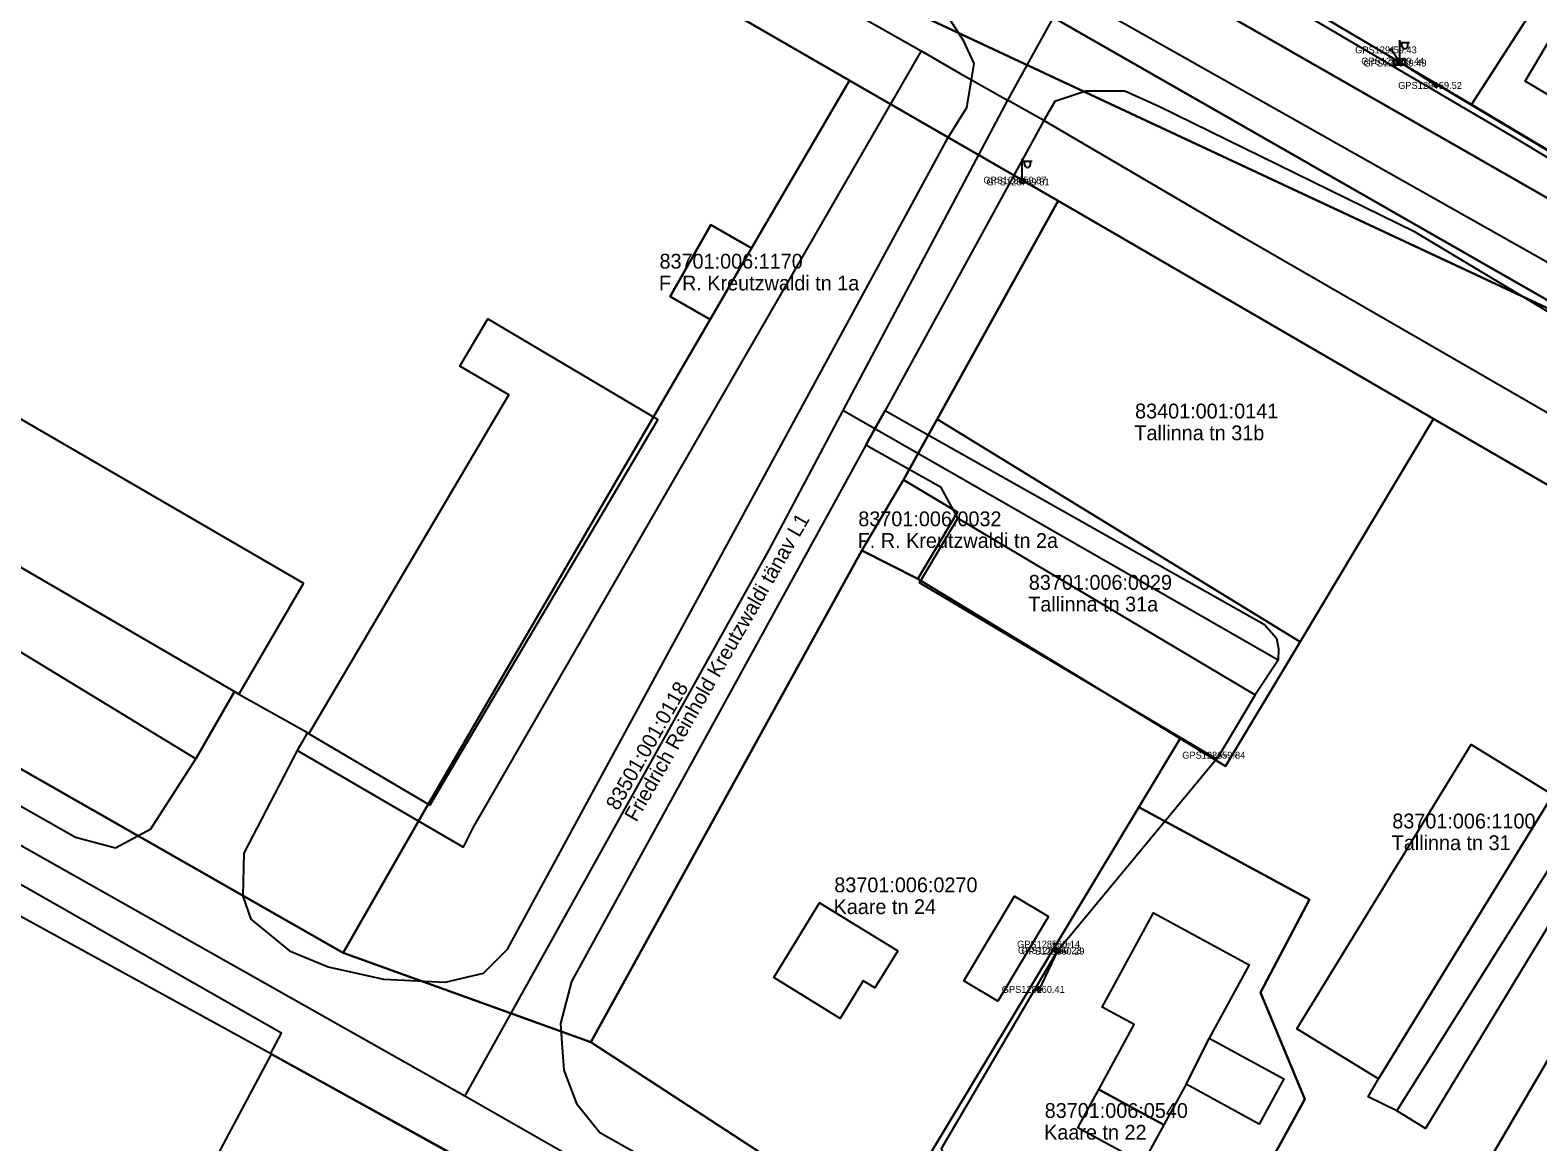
# Model space of a CAD drawing. Extents: x 580119 to 583377, y 6518915 to 6520820.
# Drawn here: x 581401 to 581553.7, y 6519827.6 to 6519940.2 of the extents above; entities that cross this region are included whole.
import ezdxf

# ---------------------------------------------------------------- set-up
doc = ezdxf.new("R2010")
doc.units = 0
for name, color, linetype in [('ELRAJATISMP', 7, 'Continuous'), ('Hoone Elu- või ühiskondlik hoone', 7, 'Continuous'), ('Hoone Kõrval- või tootmishoone', 7, 'Continuous'), ('Hoone Vare', 7, 'Continuous'), ('L_AADRESS', 7, 'Continuous'), ('MAAMUDEL', 7, 'Continuous'), ('MOOTKORG-EH2000', 7, 'Continuous'), ('MOOTMPUNKT', 7, 'Continuous'), ('MOOTNR', 7, 'Continuous'), ('MPOHULIIN', 7, 'Continuous'), ('PIIR', 7, 'Continuous'), ('POST', 7, 'Continuous'), ('SIOHULIIN', 7, 'Continuous'), ('Tee Kergliiklustee Püsikate', 7, 'Continuous'), ('Tee Liiklusala', 7, 'Continuous'), ('Tee Muu', 7, 'Continuous'), ('Tee Rada Püsikate', 7, 'Continuous'), ('Tee Tugimaantee Püsikate', 7, 'Continuous'), ('Tee Tänav Püsikate', 7, 'Continuous'), ('TUNNUS', 7, 'Continuous')]:
    doc.layers.add(name, color=color, linetype=linetype)

msp = doc.modelspace()

# ---------------------------------------------------------------- linework, layer by layer
at = {"layer": 'ELRAJATISMP'}
for p, q in [((581539.58, 6519937.29), (581539.58, 6519936.69)), ((581539.85, 6519937.29), (581539.85, 6519936.69))]:
    msp.add_line(p, q, dxfattribs=at)
msp.add_lwpolyline([(581539.12, 6519937.29), (581540.31, 6519937.29), (581540.31, 6519936.69), (581539.12, 6519936.69)], close=True, dxfattribs=at)
at = {"layer": 'Hoone Elu- või ühiskondlik hoone'}
for points in [[(581570.8, 6519937.3), (581565.05, 6519927.58), (581552.43, 6519935.06), (581558.18, 6519944.76)], [(581428.69, 6519884.2), (581422.17, 6519872.97), (581382.36, 6519896.1), (581389.59, 6519908.57), (581397.85, 6519903.79), (581397.12, 6519902.55)], [(581555.24, 6519862.76), (581537.58, 6519833.98), (581529.3, 6519839.06), (581546.95, 6519867.85)], [(581488.88, 6519846.95), (581486.57, 6519843.2), (581485.39, 6519843.92), (581483.04, 6519840.1), (581476.32, 6519844.25), (581480.97, 6519851.81)], [(581515.84, 6519829.32), (581509.24, 6519832.92), (581512.82, 6519839.5), (581509.6, 6519841.25), (581514.8, 6519850.82), (581524.48, 6519845.55), (581520.42, 6519838.11), (581518.08, 6519833.44)]]:
    msp.add_lwpolyline(points, close=True, dxfattribs=at)
at = {"layer": 'Hoone Kõrval- või tootmishoone'}
for points in [[(581464.6, 6519900.79), (581441.5, 6519861.7), (581429.23, 6519868.95), (581449.51, 6519903.28), (581444.55, 6519906.21), (581447.36, 6519910.98)], [(581525.08, 6519872.9), (581521.2, 6519866.37), (581517.32, 6519868.67), (581491.08, 6519884.26), (581494.96, 6519890.8)], [(581504.14, 6519850.43), (581499.02, 6519841.86), (581495.58, 6519843.91), (581500.7, 6519852.48)]]:
    msp.add_lwpolyline(points, close=True, dxfattribs=at)
at = {"layer": 'Hoone Vare'}
for points in [[(581518.08, 6519833.44), (581520.42, 6519838.11), (581528, 6519833.99), (581525.5, 6519829.4)], [(581515.84, 6519829.32), (581513.72, 6519825.43), (581507.12, 6519829.03), (581509.24, 6519832.92)]]:
    msp.add_lwpolyline(points, close=True, dxfattribs=at)
at = {"layer": 'MOOTMPUNKT'}
for centre in [(581538.85, 6519938.24), (581539.61, 6519937.1), (581539.83, 6519936.91), (581543.42, 6519934.64), (581501.34, 6519925.04), (581501.66, 6519924.86), (581521.48, 6519866.78), (581504.75, 6519847.63), (581504.91, 6519847.01), (581505.19, 6519846.93), (581503.2, 6519843.05)]:
    msp.add_circle(centre, 0.1, dxfattribs=at)
at = {"layer": 'MPOHULIIN'}
for p, q in [((581539.72, 6519936.99), (581538.84, 6519938.23)), ((581505.05, 6519846.97), (581504.75, 6519847.63))]:
    msp.add_line(p, q, dxfattribs=at)
for points in [[(581386.07, 6520026.02), (581416.88, 6520008.2), (581446.3, 6519991.39), (581473.57, 6519975.61), (581504.78, 6519957.66), (581539.72, 6519936.99), (581580.34, 6519912.71), (581617.8, 6519889.38), (581651.14, 6519869.54), (581688.96, 6519846.82), (581727.78, 6519823.51), (581768.99, 6519798.83), (581799.65, 6519780), (581800.76, 6519769.03)], [(581506.27, 6519795.87), (581493.32, 6519826.92), (581505.05, 6519846.97), (581521.48, 6519866.78)]]:
    msp.add_lwpolyline(points, dxfattribs=at)
at = {"layer": 'PIIR'}
for points in [[(580934.22, 6520137.63), (580961.6, 6520119.91), (581036.65, 6520071.34), (581053.81, 6520065.12), (581084.53, 6520048.5), (581102.35, 6520038.3), (581107.85, 6520035.21), (581145.57, 6520014.29), (581199.14, 6519985.02), (581203.14, 6519992.08), (581214.93, 6519985.52), (581213.15, 6519973.93), (581310.08, 6519918.55), (581308.73, 6519916.22), (581335.95, 6519901.99), (581432.72, 6519846.75), (581457.82, 6519837.71), (581487.37, 6519818.42)], [(581454.3, 6519820.58), (581425.45, 6519836.48), (581361.73, 6519871.48), (581318.74, 6519895.63), (581284.47, 6519914.76), (581242.55, 6519938.16), (581227.33, 6519946.35), (581201.89, 6519954.96), (581178.55, 6519968.04), (581120.97, 6519999.1), (581116.22, 6520001.73), (581059.63, 6520033.73), (581028.78, 6520051.18), (581019.31, 6520065.37), (580969.35, 6520097.64), (580930.16, 6520122.91)], [(581689.84, 6519815.63), (581631.91, 6519849.33), (581575.03, 6519882.38), (581543.14, 6519900.86), (581505.13, 6519922.94), (581483.99, 6519935.14), (581314, 6520033.36)], [(581761.13, 6519789.94), (581562.34, 6519908.5), (581363.85, 6520022.11), (581368.33, 6520029.92), (581566.91, 6519916.24), (581765.76, 6519797.71)], [(581765.76, 6519797.71), (581566.91, 6519916.24), (581368.33, 6520029.92)], [(581386.35, 6520025.87), (581417.16, 6520008.29), (581442.14, 6519993.86), (581446.53, 6519991.3), (581473.92, 6519975.28), (581505.33, 6519957.51), (581518.19, 6519949.74), (581546.98, 6519932.72), (581562.55, 6519923.42), (581578.78, 6519913.69), (581589.04, 6519907.54), (581618.38, 6519889.95), (581645.47, 6519873.21), (581677.12, 6519854.1), (581713.07, 6519832.45), (581720.83, 6519828.38), (581751.53, 6519809.56)], [(581385.98, 6520004.33), (581488.8, 6519942.86), (581562.34, 6519908.5), (581761.13, 6519789.94)]]:
    msp.add_lwpolyline(points, dxfattribs=at)
for points in [[(581314, 6520033.36), (581483.99, 6519935.14), (581474.08, 6519918.16), (581469.95, 6519920.52), (581465.84, 6519913.25), (581469.89, 6519910.94), (581441.15, 6519861.53), (581432.72, 6519846.75), (581335.95, 6519901.99), (581308.73, 6519916.22), (581310.08, 6519918.55), (581213.15, 6519973.93), (581214.93, 6519985.52), (581215, 6519986.31), (581250.08, 6520048.4), (581263.65, 6520040.92), (581266.61, 6520041.64), (581256.22, 6520026.21), (581295.9, 6520003.32)], [(581363.85, 6520022.11), (581562.34, 6519908.5), (581488.8, 6519942.86), (581385.98, 6520004.33)], [(581537.65, 6519985.4), (581566.98, 6519967.38), (581568.58, 6519966.17), (581546.98, 6519932.72), (581518.19, 6519949.74)], [(581546.98, 6519932.72), (581568.58, 6519966.17), (581583.23, 6519957.18), (581562.55, 6519923.42)], [(581474.08, 6519918.16), (581483.99, 6519935.14), (581505.13, 6519922.94), (581492.88, 6519900.83), (581489.47, 6519894.69), (581485.24, 6519887.52), (581457.82, 6519837.71), (581432.72, 6519846.75), (581441.15, 6519861.53), (581469.89, 6519910.94)], [(581529.63, 6519878.27), (581492.88, 6519900.83), (581505.13, 6519922.94), (581543.14, 6519900.86)], [(581469.95, 6519920.52), (581474.08, 6519918.16), (581469.89, 6519910.94), (581465.84, 6519913.25)], [(581513.81, 6519802.22), (581530.13, 6519831.94), (581525.61, 6519842.75), (581530.57, 6519852.17), (581513.31, 6519861.5), (581517.49, 6519868.48), (581522.09, 6519865.67), (581529.63, 6519878.27), (581543.14, 6519900.86), (581575.03, 6519882.38), (581561.83, 6519859.69), (581574.89, 6519851.77), (581563.53, 6519832.71), (581555.45, 6519837.16), (581529.53, 6519792.85)], [(581492.88, 6519900.83), (581529.63, 6519878.27), (581522.09, 6519865.67), (581517.49, 6519868.48), (581490.92, 6519884.64), (581494.94, 6519891.4), (581489.47, 6519894.69)], [(581489.47, 6519894.69), (581494.94, 6519891.4), (581490.92, 6519884.64), (581485.24, 6519887.52)], [(581485.24, 6519887.52), (581490.92, 6519884.64), (581517.49, 6519868.48), (581513.31, 6519861.5), (581487.37, 6519818.42), (581457.82, 6519837.71)], [(581513.31, 6519861.5), (581530.57, 6519852.17), (581525.61, 6519842.75), (581530.13, 6519831.94), (581513.81, 6519802.22), (581487.37, 6519818.42)], [(581529.53, 6519792.85), (581555.45, 6519837.16), (581563.53, 6519832.71), (581572.2, 6519827.94), (581544.38, 6519782.68)], [(581454.3, 6519820.58), (581392.36, 6519702.02), (581363.12, 6519718.9), (581368.12, 6519728.97), (581425.45, 6519836.48)]]:
    msp.add_lwpolyline(points, close=True, dxfattribs=at)
at = {"layer": 'POST'}
for p, q in [((581539.72, 6519937.24), (581539.72, 6519939.24)), ((581539.72, 6519938.99), (581540.72, 6519938.99)), ((581539.94, 6519938.67), (581539.94, 6519938.99)), ((581540.56, 6519938.67), (581540.56, 6519938.99)), ((581539.72, 6519936.99), (581539.72, 6519936.99)), ((581501.5, 6519925.2), (581501.5, 6519927.2)), ((581501.5, 6519926.95), (581502.5, 6519926.95)), ((581501.73, 6519926.63), (581501.73, 6519926.95)), ((581502.34, 6519926.63), (581502.34, 6519926.95)), ((581501.5, 6519924.95), (581501.5, 6519924.95))]:
    msp.add_line(p, q, dxfattribs=at)
for points in [[(581543.42, 6519934.64), (581539.72, 6519937)], [(581505.05, 6519846.97), (581503.2, 6519843.05)]]:
    msp.add_lwpolyline(points, dxfattribs=at)
for centre, radius in [((581539.72, 6519936.99), 0.25), ((581543.42, 6519934.64), 0.2), ((581501.5, 6519924.95), 0.25), ((581501.5, 6519924.95), 0.225), ((581501.5, 6519924.95), 0.2), ((581501.5, 6519924.95), 0.175), ((581501.5, 6519924.95), 0.15), ((581501.5, 6519924.95), 0.125), ((581501.5, 6519924.95), 0.1), ((581501.5, 6519924.95), 0.075), ((581501.5, 6519924.95), 0.05), ((581501.5, 6519924.95), 0.025), ((581505.05, 6519846.97), 0.25), ((581503.2, 6519843.05), 0.2)]:
    msp.add_circle(centre, radius, dxfattribs=at)
for centre in [(581540.25, 6519938.67), (581502.03, 6519926.63)]:
    msp.add_arc(centre, 0.306, 180, 0, dxfattribs=at)
at = {"layer": 'SIOHULIIN'}
msp.add_lwpolyline([(581504.78, 6519957.66), (581539.72, 6519936.99), (581580.34, 6519912.71), (581617.8, 6519889.38), (581651.14, 6519869.54), (581688.96, 6519846.82), (581727.78, 6519823.51), (581768.99, 6519798.83), (581799.65, 6519780)], dxfattribs=at)
at = {"layer": 'Tee Kergliiklustee Püsikate'}
for points in [[(581270.06, 6520065), (581303.35, 6520046.09), (581363.49, 6520010.55), (581381.91, 6520000), (581491.25, 6519938.16)], [(581491.25, 6519938.16), (581495.2, 6519935.86), (581496.34, 6519935.21), (581500.01, 6519933.13)], [(581576.03, 6519888.98), (581573.8, 6519890.44), (581524.01, 6519919.17), (581503.69, 6519931.09), (581500.01, 6519933.13)]]:
    msp.add_lwpolyline(points, dxfattribs=at)
at = {"layer": 'Tee Liiklusala'}
for points in [[(581591.06, 6520100.92), (581558.91, 6520038.28), (581538.3, 6519999.86), (581516.71, 6519957.56), (581515.42, 6519954.12), (581514.85, 6519951.12), (581517.94, 6519949.01), (581550.94, 6519929.6), (581576.02, 6519914.52), (581578.66, 6519913.39), (581581.86, 6519912.82), (581583.74, 6519915.13), (581607.99, 6519955.45), (581634.21, 6520000), (581654.01, 6520034.24), (581661.67, 6520046.25)], [(581307.75, 6519914.05), (581405.61, 6519858.46), (581409.68, 6519857.39), (581413.24, 6519859.32), (581417.81, 6519866.42), (581421.72, 6519873.23), (581422.17, 6519872.97), (581429.11, 6519869.07), (581428.52, 6519868.06), (581428.08, 6519867.25), (581422.66, 6519856.85), (581422.55, 6519852.51), (581423.37, 6519850.16), (581427.27, 6519846.97), (581431.19, 6519845.35), (581436.79, 6519844.1), (581443.05, 6519843.77), (581446.95, 6519844.7), (581449.37, 6519847.12), (581494, 6519929.35), (581495.88, 6519932.39), (581496.34, 6519935.21), (581496.61, 6519936.86), (581495.59, 6519939.13), (581492.27, 6519944.31)], [(581454.63, 6519820.32), (581425.37, 6519836.51), (581426.46, 6519838.63), (581388.93, 6519859.99), (581372.52, 6519869.5), (581367.27, 6519872.42), (581364.21, 6519872.46), (581361.8, 6519871.26), (581357.99, 6519864.77), (581334.18, 6519878.16), (581338.49, 6519886.29), (581338.05, 6519888.19), (581336.92, 6519889.56), (581320.88, 6519898.91), (581316.77, 6519901.3), (581306.43, 6519907.04), (581286.61, 6519918.02), (581283.94, 6519919.5), (581277.28, 6519923.19), (581246.66, 6519940.19)], [(581574, 6519900.15), (581541.28, 6519919.76), (581515.34, 6519932.51), (581511.87, 6519934.07), (581507.95, 6519934.07), (581504.78, 6519933.01), (581503.69, 6519931.09), (581487.6, 6519901.71), (581486.57, 6519899.83), (581485.67, 6519898.2), (581480.89, 6519889.5), (581455.86, 6519843.86), (581454.73, 6519839.58), (581454.91, 6519837.14), (581455.08, 6519834.85), (581456.34, 6519831.49), (581458.72, 6519828.55), (581489.68, 6519811.11)], [(581567.06, 6519869.73), (581542.34, 6519828.95), (581539.42, 6519830.74), (581536.52, 6519832.18), (581537.58, 6519833.98), (581555.24, 6519862.76)]]:
    msp.add_lwpolyline(points, dxfattribs=at)
at = {"layer": 'Tee Muu'}
for points in [[(581421.72, 6519873.23), (581417.81, 6519866.42), (581376.92, 6519891.29), (581373.93, 6519887.02), (581372.23, 6519886.59), (581369.67, 6519887.88), (581319.76, 6519916.9), (581320.18, 6519919.04), (581325.99, 6519928.86), (581318.2, 6519933.38), (581317.3, 6519931.84), (581301.19, 6519941.21), (581308.15, 6519953.17), (581324.39, 6519943.74), (581334.27, 6519960.75), (581366.54, 6519942), (581360.05, 6519930.82), (581391.8, 6519912.38), (581389.59, 6519908.57), (581382.36, 6519896.1)], [(581517.32, 6519868.67), (581491.08, 6519884.26), (581494.96, 6519890.8), (581493.28, 6519893.91), (581485.67, 6519898.2), (581486.57, 6519899.83), (581487.6, 6519901.71), (581489.81, 6519900.46), (581526.02, 6519880.03), (581527.25, 6519878.64), (581527.46, 6519877.57), (581527.42, 6519876.41), (581525.08, 6519872.9), (581521.2, 6519866.37)]]:
    msp.add_lwpolyline(points, close=True, dxfattribs=at)
at = {"layer": 'Tee Rada Püsikate'}
msp.add_lwpolyline([(581491.25, 6519938.16), (581488.23, 6519932.88), (581445.89, 6519859.5), (581444.87, 6519857.46), (581428.08, 6519867.25)], dxfattribs=at)
at = {"layer": 'Tee Tugimaantee Püsikate'}
msp.add_lwpolyline([(581506.09, 6519944.2), (581577.51, 6519903.87), (581580.61, 6519901.98)], dxfattribs=at)
at = {"layer": 'Tee Tänav Püsikate'}
for points in [[(581246.66, 6519944.17), (581285.63, 6519921.96), (581307.88, 6519909.66), (581410.64, 6519851.69), (581445.06, 6519832.27)], [(581506.09, 6519944.2), (581500.01, 6519933.13)], [(581500.01, 6519933.13), (581483.32, 6519901.7)], [(581483.32, 6519901.7), (581475.78, 6519887.51), (581445.06, 6519832.27)], [(581527.42, 6519876.41), (581486.57, 6519899.83), (581483.32, 6519901.7)], [(581539.42, 6519830.74), (581576.03, 6519888.98)], [(581445.06, 6519832.27), (581458.04, 6519824.84), (581465.83, 6519820.54)]]:
    msp.add_lwpolyline(points, dxfattribs=at)

# ---------------------------------------------------------------- texts
at = {"layer": 'L_AADRESS'}
for s, p in [('F. R. Kreutzwaldi tn 1a', (581464.7, 6519913.87)), ('Tallinna tn 31b', (581512.85, 6519898.69)), ('F. R. Kreutzwaldi tn 2a', (581484.83, 6519887.78)), ('Tallinna tn 31a', (581502.1, 6519881.34)), ('Tallinna tn 31', (581538.91, 6519857.16)), ('Kaare tn 24', (581482.39, 6519850.68)), ('Kaare tn 22', (581503.71, 6519827.83))]:
    msp.add_text(s, height=1.5, dxfattribs=at).set_placement(p)
msp.add_text('Friedrich Reinhold Kreutzwaldi tänav L1', height=1.5, rotation=60.2429, dxfattribs=at).set_placement((581462.42, 6519859.93))
at = {"layer": 'MAAMUDEL'}
for s, p in [(' mp_ohl', (581521.48, 6519866.6)), (' mp_ohl', (581504.75, 6519847.46)), (' kilp', (581504.91, 6519846.84)), (' kilp', (581505.19, 6519846.75))]:
    msp.add_text(s, height=0.35, dxfattribs=at).set_placement(p)
at = {"layer": 'MOOTKORG-EH2000'}
for s, p in [(' 59.43', (581538.85, 6519937.89)), (' 59.44', (581539.61, 6519936.75)), (' 59.49', (581539.83, 6519936.56)), (' 59.52', (581543.42, 6519934.29)), (' 59.87', (581501.34, 6519924.69)), (' 59.81', (581501.66, 6519924.51)), (' 59.84', (581521.48, 6519866.43)), (' 60.14', (581504.75, 6519847.28)), (' 60.23', (581504.91, 6519846.66)), (' 60.29', (581505.19, 6519846.58)), (' 60.41', (581503.2, 6519842.7))]:
    msp.add_text(s, height=0.7, dxfattribs=at).set_placement(p)
at = {"layer": 'MOOTNR'}
for s, p in [('GPS1291 ', (581535.21, 6519937.89)), ('GPS1292 ', (581535.83, 6519936.75)), ('GPS1293 ', (581536.05, 6519936.56)), ('GPS1294 ', (581539.57, 6519934.29)), ('GPS1288 ', (581497.56, 6519924.69)), ('GPS1287 ', (581497.88, 6519924.51)), ('GPS1286 ', (581517.7, 6519866.43)), ('GPS1285 ', (581500.97, 6519847.28)), ('GPS1284 ', (581501.06, 6519846.66)), ('GPS1283 ', (581501.41, 6519846.58)), ('GPS1282 ', (581499.42, 6519842.7))]:
    msp.add_text(s, height=0.7, dxfattribs=at).set_placement(p)
at = {"layer": 'TUNNUS'}
for s, p in [('83701:006:1170', (581464.76, 6519916.08)), ('83401:001:0141', (581512.92, 6519900.9)), ('83701:006:0032', (581484.89, 6519889.98)), ('83701:006:0029', (581502.16, 6519883.54)), ('83701:006:1100', (581538.97, 6519859.36)), ('83701:006:0270', (581482.46, 6519852.89)), ('83701:006:0540', (581503.77, 6519830.03))]:
    msp.add_text(s, height=1.5, dxfattribs=at).set_placement(p)
msp.add_text('83501:001:0118', height=1.5, rotation=60.2429, dxfattribs=at).set_placement((581460.54, 6519861.08))

doc.saveas('drawing.dxf')
